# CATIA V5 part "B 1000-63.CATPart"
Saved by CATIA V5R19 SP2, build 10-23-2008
Part number: B 1000-63
Bounding box of the stored display mesh (mm): x -24.865 to 24.865, y -24.997 to 24.997, z 0 to 222
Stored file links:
  C:\Users\Bora\Desktop\3D Katı model\B serisi\B 1000\B 1000-63.CATPart
  C:\Program Files\Dassault Systemes\B19\intel_a\reffiles\standard\MetricThickPitch.txt
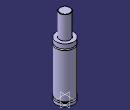
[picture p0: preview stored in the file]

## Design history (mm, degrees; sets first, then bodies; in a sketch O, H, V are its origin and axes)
Body1 (main body)
  Sketch1 on yz-plane, origin (0, 0, 0), H (0, 1, 0), V (0, 0, 1)
    point P3 (15, 221)
    point P5 (15, 221)
    point P10 (25, 139.5)
    point P11 (25, 143.5)
    point P13 (25, 143.5)
    point P14 (25, 139.5)
    line L1 (25, 0) -> (25, 8)
    line L2 (15, 221) -> (15, 156)
    arc A1 centre (14, 221) radius 1 from (15, 221) to (14, 222) ccw
    line L3 (21.5, 13) -> (21.5, 8)
    line L4 (25, 13) -> (25, 139.5)
    line L5 (25, 143.5) -> (25, 156)
    arc A2 centre (25, 141.5) radius 2 from (25, 143.5) to (25, 139.5) ccw
    line L6 (14, 222) -> (0, 222)
    point P15 (0, 222)
    line L7 (15, 156) -> (25, 156)
    line L8 (0, 0) -> (25, 0)
    line L9 (21.5, 13) -> (25, 13)
    line L10 (21.5, 8) -> (25, 8)
    coincidence: P15 V, P3 P5, P10 P14, P11 P13
    tangency: L6 A1
    horizontal: L7 H, L8 H, L9 H, L10 H
  Shaft1: profile Sketch1, axis Sketch1.V, angle 360
  Sketch2 on face of Shaft1 from Sketch1.L8, origin (0, 0, 0), H (1, 0, 0), V (0, -1, 0)
    point P1 (10, 0)
    distance P1 V = 10
  Hole1: placed by Sketch2, at (10, 0, 0) direction (0, 0, 1), diameter 6.647, depth 13, threaded "M8", thread diameter 8, thread depth 13, pitch 1.25
  CircPattern1: of Hole1, instances 2, angular step 180, axis from xy-plane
